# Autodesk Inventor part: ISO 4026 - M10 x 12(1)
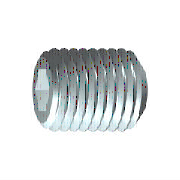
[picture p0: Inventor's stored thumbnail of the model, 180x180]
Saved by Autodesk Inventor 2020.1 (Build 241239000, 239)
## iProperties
Created: 2019-01
Part Number: ISO 4026 - M10 x 12(1)
Material: Edelstahl, 440C
Description: Innensechskant-Gewindestifte mit Kegelstumpf
Document SubType Name: Modeling
Standard: ISO 4026
Designer: lutzd
Standard Revision: Third edition 2003-12-01
Standards Organization: ISO
Language: de-DE
Size Designation: M10 x 12
Categories: <MemberInstance><Categories><Category DisplayName="Verbindungselemente" InternalName="e4da775c-781d-43d5-af7c-5136215cf5a6" Mnemonic="FSTN"><Category DisplayNam
Mass: 5.99431 g
Surface Area: 6.07812 cm^2
Volume: 0.77346 cm^3
Density: 7.75 g/cm^3
Appearance: Semi-Polished(3)
IsCustomPart: 0
Author: lutzd
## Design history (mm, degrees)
sketch "Skizze1"
  geometry: L1 (0, 0)-(4.333, 0); L2 (12, 2.887)-(12, 5); L3 (12, 5)-(0, 5); L4 (12, 2.887)-(6, 2.887); L5 (6, 2.887)-(4.333, 0); L6 (0, -1)-(0, 6) reference; L7 (0, 5)-(0, 0)
  constraints: 13 end point, 3 parallel, 1 collinear, 1 perpendicular, 1 point on line
  dimensions: "d0" = 6 distance of L2.start L4.end (= INTI); "d1" = 60 deg angle of L5 L1; "d2" = 10 diameter of L3 L1 (= NND); "d3" = 5.7735 diameter of L4 L1 (= 1.1547 x SW); "d5" = 12 distance from line of L2 L3.end (= NLG)
revolve "Körper" sketch "Skizze1" stored, may be unused: angle "d6" = 90 deg
sketch "Skizze2"
  geometry: L1 (-1.443, 2.5)-(1.443, 2.5); L2 (1.443, 2.5)-(2.887, 0); L3 (2.887, 0)-(1.443, -2.5); L4 (1.443, -2.5)-(-1.443, -2.5); L5 (-1.443, -2.5)-(-2.887, 0); L6 (-2.887, 0)-(-1.443, 2.5); A1 r 2.887 centre (0, 0) between (-1.443, 2.5) and (1.443, 2.5) reference; 2 further points
  constraints: 12 end point, 2 point on circle, 1 coincident, 1 horizontal, 11 other
extrude "Loch" join sketch "Skizze2" taper "d9" = 0 deg; stored distance "d21" = 10
workaxis "Work Axis1"
workplane "Work Plane1"
body "Solid1"
chamfer "Fase1" distance "d7" = 0.92018 (= -0.5 x GD1 + 0.5 x NND); stored, may be unused: angle "d8" = 45 deg (= FAWI), second distance "d29" = 0.92018 (= -0.5 x GD1 + 0.5 x NND)
feature "Gewinde" dims "d11" = 12 (= NLG), "d12" = 0
chamfer "Fase2" distance "d13" = 0.92018 (= -0.5 x GD1 + 0.5 x NND); stored, may be unused: angle "d14" = 45 deg (= FAWI), second distance "d30" = 0.92018 (= -0.5 x GD1 + 0.5 x NND)
other parameters: "NND" = 10 [user parameter; used in 5 equation terms], "NLG" = 12 [user parameter; used in 2 equation terms], "INTI" = 6 [user parameter; used in 1 equation term], "FAWI" = 45 deg [user parameter; used in 2 equation terms], "SW" = 5 [user parameter; used in 2 equation terms], "GD1" = 8.15965 (= THREADDIA - 1.2269 x PTC) [user parameter; used in 4 equation terms], "d4" = 0, "FAWI1" = 45 deg [user parameter], "d15" = 0, "d31" = 0, "GUL" = 0.92018 (= 0.61345 x PTC) [user parameter], "SPD" = 7 [user parameter], "SEWI" = 90 deg [user parameter], "TOA" = 30 deg [user parameter], "TPU" = 6.66667 (computed from PTC) [user parameter], "PTC" = 1.5 [user parameter; used in 4 equation terms], "GAL" = 0.92018 (= 0.61345 x PTC) [user parameter], "E0" = 5.775 (= 1.155 x SW) [user parameter]
